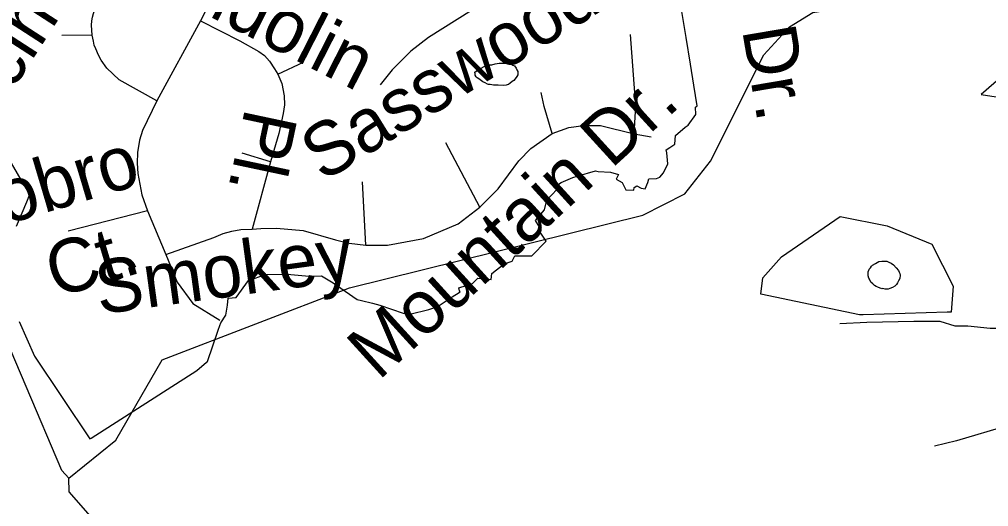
# Model space of a CAD drawing. Extents: x 2001466 to 31450019, y -30647475 to 847247.
# Drawn here: x 2193786 to 2197224, y 751177 to 752905 of the extents above; entities that cross this region are included whole.
import ezdxf

# ---------------------------------------------------------------- set-up
doc = ezdxf.new("R2010")
doc.units = 0
for name, color, linetype in [('Exist Boundary Political City Limit New', 7, 'Continuous'), ('Exist Hydrographic Creek Single Shore', 7, 'Continuous'), ('Exist Hydrographic Misc Water Feature', 7, 'Continuous'), ('Exist Road Non-System Type 51', 7, 'Continuous'), ('Exist Road Non-System Type 51 Label', 7, 'Continuous'), ('Map Preparation Boundary City Limit Buffer Line', 7, 'Continuous')]:
    doc.layers.add(name, color=color, linetype=linetype)

msp = doc.modelspace()

# ---------------------------------------------------------------- linework, layer by layer
at = {"layer": 'Exist Boundary Political City Limit New'}
for points in [[(2195990.8, 752306.6), (2196005, 752304.9), (2196015.2, 752326.6), (2196018.5, 752340), (2196045.8, 752340.6), (2196058, 752345.9), (2196070, 752361.6), (2196085.5, 752393.3), (2196082.8, 752431.8), (2196080, 752442.6), (2196093.5, 752451.1), (2196111, 752462.2), (2196113.5, 752493.8), (2196147.5, 752523.2), (2196158.2, 752530.4), (2196185.5, 752568.3), (2196184, 752593.5), (2196190, 752598.6), (2196178, 752672.6), (2196165.8, 752747.1), (2196150.5, 752841.3), (2196133.2, 752947)], [(2197476.5, 752881.3), (2197197.2, 752638.6), (2198374.8, 752457.2)], [(2193627.2, 752617.8), (2193791.2, 752336.1), (2193822.5, 752283.7), (2193811, 752256.5), (2193775, 752170.3)], [(2193785.8, 751833.8), (2193839.2, 751710.3), (2194035.5, 751417.2), (2194040.2, 751420.1), (2194415.8, 751659.9), (2194450, 751689.1), (2194453, 751691.5), (2194491.5, 751803.4), (2194497.2, 751819.8), (2194500.2, 751828.6), (2194518.5, 751856.4), (2194524.5, 751891.4), (2194526.5, 751916.7), (2194555.5, 751918.4), (2194599, 751979.6), (2194658.5, 752000.8), (2194736, 752001.9), (2194813.5, 751994.6), (2194857.5, 751995.6), (2194898.8, 751971.2), (2194984.5, 751912.3), (2195000, 751908.2), (2195038.5, 751898.3), (2195064.8, 751891.4), (2195147, 751863.3), (2195170.8, 751859.3), (2195237.8, 751876.3), (2195268, 751886.2), (2195320.5, 751921), (2195346, 751937.1), (2195348.8, 751938.8), (2195347.5, 751942.2), (2195344.2, 751952.9), (2195393.5, 751968), (2195411.8, 751987.4), (2195459.2, 751983.2), (2195461.2, 752003.4), (2195505.5, 752037.9), (2195533.8, 752048.1), (2195542.8, 752066.8), (2195604, 752066.8), (2195654.5, 752119.1), (2195627.8, 752157.4), (2195630, 752170.7), (2195616.8, 752192.1), (2195648.5, 752230.2), (2195656.5, 752264.2), (2195692, 752302.2), (2195691.5, 752316.4), (2195707.5, 752326.2), (2195749, 752344.6), (2195764.2, 752349.6), (2195829, 752368.7), (2195839.2, 752365.9), (2195882.5, 752364), (2195910.5, 752354.8), (2195902.5, 752338.4), (2195924.2, 752326.9), (2195937.2, 752300.4), (2195965, 752299.4), (2195966, 752308.7), (2195976, 752314.5), (2195990.8, 752306.6)]]:
    msp.add_lwpolyline(points, dxfattribs=at)
at = {"layer": 'Exist Hydrographic Creek Single Shore'}
for points in [[(2193961.9, 751278.4), (2193936.9, 751305.2), (2193682.9, 751900.9), (2193680.8, 752127.2), (2193705.8, 752195.6), (2193688, 752337.1), (2193570.9, 752460.8), (2193462.8, 752449.9), (2193297, 752374.6), (2192904.9, 752362.9)], [(2193773.9, 749638.9), (2193704.8, 749853.5), (2193655, 749936.5), (2193646, 750051.6), (2193894.9, 750171.1), (2193993.9, 750270.8), (2194175, 750555.7), (2194182, 750749.1), (2194071.8, 751105.6), (2193963, 751229.2), (2193961.9, 751278.4)]]:
    msp.add_lwpolyline(points, dxfattribs=at)
at = {"layer": 'Exist Hydrographic Misc Water Feature'}
msp.add_line((2197076.2, 751866.7), (2196778.7, 751857.8), dxfattribs=at)
for points in [[(2193961.9, 751278.4), (2194127.8, 751412.8), (2194292.9, 751698.1), (2194956.9, 751953.5), (2195996.9, 752211), (2196146, 752286.6), (2196236.8, 752402.9), (2196425.8, 752779.5), (2196516.9, 752879.3), (2196599.9, 752930.1), (2196823.9, 752964.8), (2196974, 753050.3), (2197147.8, 753210.8), (2197570.9, 753402.2), (2197976.9, 753705.5), (2198038.3, 753737.8)], [(2195554, 752708.8), (2195550.1, 752702.9), (2195548, 752698.8), (2195540, 752688.6), (2195533.9, 752684.7), (2195526.1, 752678.6), (2195520.3, 752674.6), (2195516.2, 752672.8), (2195512.3, 752672.5), (2195502.1, 752670.4), (2195484.2, 752672.3), (2195468, 752672.3), (2195456, 752674.2), (2195450.2, 752674.2), (2195446.1, 752676.1), (2195437.9, 752680.1), (2195430.1, 752684.2), (2195416, 752694), (2195410.2, 752697.7), (2195406.3, 752702), (2195402.2, 752707.9), (2195402, 752712), (2195401.6, 752717.6), (2195405.7, 752721.9), (2195411.9, 752725.8), (2195424, 752732.2), (2195434, 752737.9), (2195446.1, 752742.2), (2195453.7, 752744.3), (2195461.7, 752744.3), (2195473.4, 752748.2), (2195487.9, 752750.5), (2195501.5, 752750.5), (2195505.8, 752750.6), (2195511.7, 752750.6), (2195521.6, 752748.6), (2195531.4, 752746.7), (2195535.9, 752742.8), (2195541.5, 752740.8), (2195547.8, 752732.9), (2195549.9, 752726.9), (2195554, 752721), (2195553.8, 752715), (2195554, 752708.8)], [(2196778.7, 751857.8), (2196766.1, 751857.4), (2196415.1, 751930.2), (2196423.1, 751989.1), (2196489.1, 752063.2), (2196697.2, 752206.6), (2196864.2, 752173.6), (2197022.1, 752108), (2197098.1, 751958.9), (2197091.2, 751867.2), (2197076.2, 751866.7)], [(2196830.6, 751955.8), (2196824.7, 751957.9), (2196818.9, 751962), (2196812.8, 751967.8), (2196806.4, 751973.6), (2196800.5, 751983.9), (2196798.6, 751987.8), (2196796.6, 751995.8), (2196796.6, 752003.5), (2196796.2, 752009.7), (2196798.6, 752015.8), (2196800.1, 752019.6), (2196804.2, 752023.9), (2196808.1, 752029.7), (2196812.2, 752034), (2196822.2, 752039.8), (2196834.3, 752046.1), (2196844.4, 752047.8), (2196854, 752047.9), (2196862.2, 752047.9), (2196870, 752044.4), (2196878.2, 752040.3), (2196886.2, 752034.2), (2196896, 752024.2), (2196904.2, 752014.4), (2196906.1, 752008.5), (2196908.5, 752004.5), (2196910.4, 751998.5), (2196910.2, 751994.5), (2196908.1, 751990.3), (2196908.5, 751986.6), (2196904.4, 751978.3), (2196900.5, 751970.3), (2196896.6, 751964.4), (2196890.5, 751958.5), (2196882.7, 751954.4), (2196872.7, 751950.2), (2196866.7, 751948.3), (2196860.4, 751948), (2196856.7, 751948.2), (2196848.9, 751950.2), (2196844.6, 751950), (2196830.6, 751955.8)]]:
    msp.add_lwpolyline(points, dxfattribs=at)
at = {"layer": 'Exist Road Non-System Type 51'}
msp.add_line((2194606.6, 753247.2), (2194428.8, 752900.3), dxfattribs=at)
for points in [[(2194044.7, 752849.4), (2194042.4, 752885.1), (2194043.3, 752900.3), (2194045.8, 752913.5), (2194049, 752926.7), (2194072.9, 752995.9), (2194122.8, 753084.6)], [(2195542.4, 753034.3), (2195237.1, 752841.6), (2195174.6, 752792.1), (2195108.7, 752726.2), (2195065.9, 752673.5)], [(2194428.8, 752900.3), (2194273.1, 752616.4)], [(2194428.8, 752900.3), (2194568, 752829.7), (2194634.8, 752791.1), (2194654.9, 752777.7), (2194673.5, 752756.9), (2194691.2, 752729.4), (2194703.2, 752710.5)], [(2194044.7, 752849.4), (2193936.2, 752848.5)], [(2194273.1, 752616.4), (2194140, 752690.8), (2194095.9, 752732.6), (2194076.6, 752761), (2194066.3, 752778.5), (2194056.9, 752800.5), (2194051.9, 752814.5), (2194048.8, 752828.4), (2194044.7, 752849.4)], [(2195966.2, 752498.9), (2195972.7, 752597.7), (2195953, 752851.5)], [(2194703.2, 752710.5), (2194793.7, 752753.6)], [(2194703.2, 752710.5), (2194716.4, 752677.5), (2194724.8, 752634.7), (2194726.4, 752602.6), (2194721.8, 752571.3), (2194705.7, 752500.3), (2194676.5, 752399.5)], [(2195676.1, 752501), (2195646.8, 752596), (2195636.8, 752646.2)], [(2194273.1, 752616.4), (2194223.3, 752511.8), (2194211.6, 752476.8), (2194205.4, 752433.4), (2194203.3, 752395.1), (2194206.4, 752358.9), (2194220.9, 752283.4), (2194240.1, 752225.7)], [(2195676.1, 752501), (2195734.6, 752522), (2195786.7, 752529.3), (2195847.6, 752528.5), (2195966.2, 752498.9)], [(2195419, 752239.4), (2195484, 752304.4), (2195557.3, 752403.5), (2195600.2, 752447.1), (2195676.1, 752501)], [(2195966.2, 752498.9), (2196027, 752488.7)], [(2195419, 752239.4), (2195298.8, 752467.8)], [(2194676.5, 752399.5), (2194576.1, 752431)], [(2194676.5, 752399.5), (2194612.1, 752161.8)], [(2195015.2, 752104.6), (2195002.4, 752328.8)], [(2194240.1, 752225.7), (2193959.6, 752154.1)], [(2194240.1, 752225.7), (2194305.6, 752071.9)], [(2195015.2, 752104.6), (2195091.2, 752105), (2195219.6, 752128), (2195342.8, 752180.6), (2195419, 752239.4)], [(2194305.6, 752071.9), (2194475.6, 752132.2), (2194508.5, 752145.3), (2194539.9, 752154), (2194571.1, 752159.5), (2194612.1, 752161.8)], [(2194612.1, 752161.8), (2194642.1, 752164), (2194697.7, 752165.3), (2194792.6, 752156.2), (2194907.8, 752123.3), (2194955.7, 752111.9), (2195015.2, 752104.6)], [(2194305.6, 752071.9), (2194345.1, 751973.8), (2194401.1, 751898), (2194496.5, 751838.7)], [(2197654.7, 751972.9), (2197679.8, 751843.5), (2197683.9, 751760), (2197683.9, 751710), (2197675.6, 751664), (2197658.9, 751639), (2197585.3, 751589), (2197450.1, 751529.8), (2197292.8, 751465), (2197109.7, 751410.8), (2197031.2, 751391.6)], [(2197050, 751835.2), (2197104.2, 751818.5), (2197150.1, 751818.5), (2197229.3, 751810.1), (2197287.7, 751810.1), (2197354.4, 751810.1), (2197442, 751839.3), (2197487.9, 751868.5), (2197546.3, 751922.8), (2197654.7, 751972.9)], [(2196695.5, 751826.8), (2196791.4, 751831), (2196958.2, 751835.2), (2197050, 751835.2)]]:
    msp.add_lwpolyline(points, dxfattribs=at)
at = {"layer": 'Map Preparation Boundary City Limit Buffer Line'}
for points in [[(2195990.8, 752306.6), (2196005, 752304.9), (2196015.2, 752326.6), (2196018.5, 752340), (2196045.8, 752340.6), (2196058, 752345.9), (2196070, 752361.6), (2196085.5, 752393.3), (2196082.8, 752431.8), (2196080, 752442.6), (2196093.5, 752451.1), (2196111, 752462.2), (2196113.5, 752493.8), (2196147.5, 752523.2), (2196158.2, 752530.4), (2196185.5, 752568.3), (2196184, 752593.5), (2196190, 752598.6), (2196178, 752672.6), (2196165.8, 752747.1), (2196150.5, 752841.3), (2196133.2, 752947)], [(2197476.5, 752881.3), (2197197.2, 752638.6), (2198374.8, 752457.2)], [(2193627.2, 752617.8), (2193791.2, 752336.1), (2193822.5, 752283.7), (2193811, 752256.5), (2193775, 752170.3)], [(2193785.8, 751833.8), (2193839.2, 751710.3), (2194035.5, 751417.2), (2194040.2, 751420.1), (2194415.8, 751659.9), (2194450, 751689.1), (2194453, 751691.5), (2194491.5, 751803.4), (2194497.2, 751819.8), (2194500.2, 751828.6), (2194518.5, 751856.4), (2194524.5, 751891.4), (2194526.5, 751916.7), (2194555.5, 751918.4), (2194599, 751979.6), (2194658.5, 752000.8), (2194736, 752001.9), (2194813.5, 751994.6), (2194857.5, 751995.6), (2194898.8, 751971.2), (2194984.5, 751912.3), (2195000, 751908.2), (2195038.5, 751898.3), (2195064.8, 751891.4), (2195147, 751863.3), (2195170.8, 751859.3), (2195237.8, 751876.3), (2195268, 751886.2), (2195320.5, 751921), (2195346, 751937.1), (2195348.8, 751938.8), (2195347.5, 751942.2), (2195344.2, 751952.9), (2195393.5, 751968), (2195411.8, 751987.4), (2195459.2, 751983.2), (2195461.2, 752003.4), (2195505.5, 752037.9), (2195533.8, 752048.1), (2195542.8, 752066.8), (2195604, 752066.8), (2195654.5, 752119.1), (2195627.8, 752157.4), (2195630, 752170.7), (2195616.8, 752192.1), (2195648.5, 752230.2), (2195656.5, 752264.2), (2195692, 752302.2), (2195691.5, 752316.4), (2195707.5, 752326.2), (2195749, 752344.6), (2195764.2, 752349.6), (2195829, 752368.7), (2195839.2, 752365.9), (2195882.5, 752364), (2195910.5, 752354.8), (2195902.5, 752338.4), (2195924.2, 752326.9), (2195937.2, 752300.4), (2195965, 752299.4), (2195966, 752308.7), (2195976, 752314.5), (2195990.8, 752306.6)]]:
    msp.add_lwpolyline(points, dxfattribs=at)

# ---------------------------------------------------------------- texts
at = {"layer": 'Exist Road Non-System Type 51 Label'}
for s, rotation, p in [('Azalea Dr.', 279.6318, (2196207, 753704.5)), ('Dulcimer Ln.', 57.1215, (2193552.4, 752328.2)), ('Mandolin', 332.9731, (2194064, 753117.5)), ('Sasswood', 31.6232, (2194862.3, 752326.4)), ('Mountain Dr.', 42.3278, (2195059.9, 751621.5)), ('Pl.', 258.0408, (2194587.6, 752595.4)), ('Dobro ', 16.6304, (2193561.4, 752124.2)), ('Ct.', 16.6304, (2193913.9, 751916.7)), ('Smokey', 7.7699, (2194068.7, 751858.7))]:
    msp.add_text(s, height=190, rotation=rotation, dxfattribs=at).set_placement(p)

doc.saveas('drawing.dxf')
